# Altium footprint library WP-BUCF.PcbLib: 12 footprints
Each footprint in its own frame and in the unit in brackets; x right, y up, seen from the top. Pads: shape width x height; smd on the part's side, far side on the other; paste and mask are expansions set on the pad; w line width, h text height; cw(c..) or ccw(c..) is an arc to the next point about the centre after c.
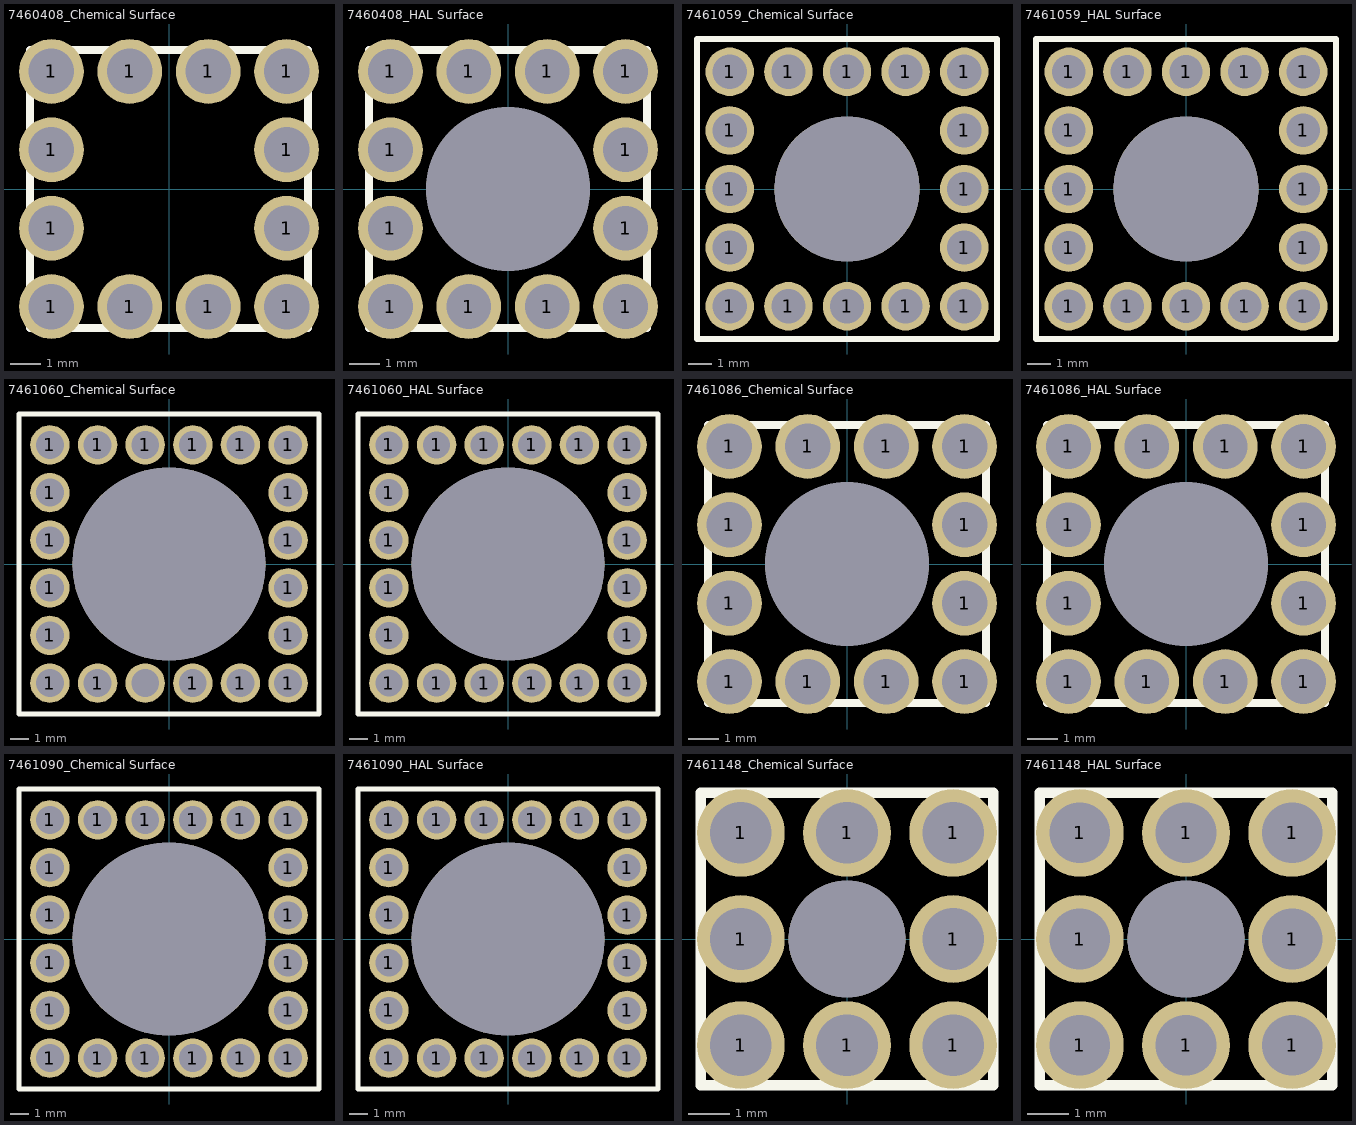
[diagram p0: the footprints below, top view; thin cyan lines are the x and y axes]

## 7460408_Chemical Surface [mm] "M5, thr 6mm"
height 9.5
pads (12):
  round 2.1 hole 1.475: 1(-3.81,-3.81) 1(-3.81,-1.27) 1(-3.81,1.27) 1(-3.81,3.81) 1(-1.27,-3.81) 1(-1.27,3.81) 1(1.27,-3.81) 1(1.27,3.81) 1(3.81,-3.81) 1(3.81,-1.27) 1(3.81,1.27) 1(3.81,3.81)
Top Overlay:
  lines w0.254: -4.5,-4.5 4.5,-4.5 4.5,4.5 -4.5,4.5 -4.5,-4.5
3D body "7460408.stp": height 6.1, standoff -3.4, extent -4.5,-4.5 4.5,4.5

## 7460408_HAL Surface [mm] "M5, thr 6mm"
height 9.5
pads (13):
  round 2.1 hole 1.45: 1(-3.81,-3.81) 1(-3.81,-1.27) 1(-3.81,1.27) 1(-3.81,3.81) 1(-1.27,-3.81) 1(-1.27,3.81) 1(1.27,-3.81) 1(1.27,3.81) 1(3.81,-3.81) 1(3.81,-1.27) 1(3.81,1.27) 1(3.81,3.81)
  round 5.3 hole 5.3 unplated: ""(0,0)
Top Overlay:
  lines w0.254: -4.5,-4.5 -4.5,4.5 4.5,4.5 4.5,-4.5 -4.5,-4.5
3D body "7460408.stp": height 6.1, standoff -3.4, extent -4.5,-4.5 4.5,4.5

## 7461059_Chemical Surface [mm] "M6, thr 13.5mm"
height 17
pads (17):
  round 2.1 hole 1.475: 1(-5.08,-5.08) 1(-5.08,-2.54) 1(-5.08,0) 1(-5.08,2.54) 1(-5.08,5.08) 1(-2.54,-5.08) 1(-2.54,5.08) 1(0,-5.08) 1(0,5.08) 1(2.54,-5.08) 1(2.54,5.08) 1(5.08,-5.08) 1(5.08,-2.54) 1(5.08,0) 1(5.08,2.54) 1(5.08,5.08)
  round 6.3 hole 6.3 unplated: ""(0,0)
Top Overlay:
  lines w0.254: -6.5,-6.5 -6.5,6.5 6.5,6.5 6.5,-6.5 -6.5,-6.5
3D body "7461059.stp": height 13.6, standoff -3.4, extent -6.5,-6.5 6.5,6.5

## 7461059_HAL Surface [mm] "M6, thr 13.5mm"
height 17
pads (17):
  round 2.1 hole 1.45: 1(-5.08,-5.08) 1(-5.08,-2.54) 1(-5.08,0) 1(-5.08,2.54) 1(-5.08,5.08) 1(-2.54,-5.08) 1(-2.54,5.08) 1(0,-5.08) 1(0,5.08) 1(2.54,-5.08) 1(2.54,5.08) 1(5.08,-5.08) 1(5.08,-2.54) 1(5.08,0) 1(5.08,2.54) 1(5.08,5.08)
  round 6.3 hole 6.3 unplated: ""(0,0)
Top Overlay:
  lines w0.254: -6.5,-6.5 6.5,-6.5 6.5,6.5 -6.5,6.5 -6.5,-6.5
3D body "7461059.stp": height 13.6, standoff -3.4, extent -6.5,-6.5 6.5,6.5

## 7461060_Chemical Surface [mm] "M10, thr 17.5mm"
height 21
pads (21):
  round 2.1 hole 1.475: 1(-6.35,-6.35) 1(-6.35,-3.81) 1(-6.35,-1.27) 1(-6.35,1.27) 1(-6.35,3.81) 1(-6.35,6.35) 1(-3.81,-6.35) 1(-3.81,6.35) 1(-1.27,6.35) 1(1.27,-6.35) 1(1.27,6.35) 1(3.81,-6.35) 1(3.81,6.35) 1(6.35,-6.35) 1(6.35,-3.81) 1(6.35,-1.27) 1(6.35,1.27) 1(6.35,3.81) 1(6.35,6.35) ""(-1.27,-6.35)
  round 10.3 hole 10.3 unplated: ""(0,0)
Top Overlay:
  lines w0.254: -8,-8 8,-8 8,8 -8,8 -8,-8
3D body "7461060.stp": height 17.6, standoff -3.4, extent -8,-8 8,8

## 7461060_HAL Surface [mm] "M10, thr 17.5mm"
height 21
pads (21):
  round 2.1 hole 1.45: 1(-6.35,-6.35) 1(-6.35,-3.81) 1(-6.35,-1.27) 1(-6.35,1.27) 1(-6.35,3.81) 1(-6.35,6.35) 1(-3.81,-6.35) 1(-3.81,6.35) 1(-1.27,-6.35) 1(-1.27,6.35) 1(1.27,-6.35) 1(1.27,6.35) 1(3.81,-6.35) 1(3.81,6.35) 1(6.35,-6.35) 1(6.35,-3.81) 1(6.35,-1.27) 1(6.35,1.27) 1(6.35,3.81) 1(6.35,6.35)
  round 10.3 hole 10.3 unplated: ""(0,0)
Top Overlay:
  lines w0.254: -8,-8 -8,8 8,8 8,-8 -8,-8
3D body "7461060.stp": height 17.6, standoff -3.4, extent -8,-8 8,8

## 7461086_Chemical Surface [mm] "M4, thr 6mm"
height 9.5
pads (13):
  round 2.1 hole 1.475: 1(-3.81,-3.81) 1(-3.81,-1.27) 1(-3.81,1.27) 1(-3.81,3.81) 1(-1.27,-3.81) 1(-1.27,3.81) 1(1.27,-3.81) 1(1.27,3.81) 1(3.81,-3.81) 1(3.81,-1.27) 1(3.81,1.27) 1(3.81,3.81)
  round 5.3 hole 5.3 unplated: ""(0,0)
Top Overlay:
  lines w0.254: -4.5,-4.5 4.5,-4.5 4.5,4.5 -4.5,4.5 -4.5,-4.5
3D body "7461086.stp": height 6.1, standoff -3.4, extent -4.5,-4.5 4.5,4.5

## 7461086_HAL Surface [mm] "M4, thr 6mm"
height 9.5
pads (13):
  round 2.1 hole 1.45: 1(-3.81,-3.81) 1(-3.81,-1.27) 1(-3.81,1.27) 1(-3.81,3.81) 1(-1.27,-3.81) 1(-1.27,3.81) 1(1.27,-3.81) 1(1.27,3.81) 1(3.81,-3.81) 1(3.81,-1.27) 1(3.81,1.27) 1(3.81,3.81)
  round 5.3 hole 5.3 unplated: ""(0,0)
Top Overlay:
  lines w0.254: -4.5,-4.5 -4.5,4.5 4.5,4.5 4.5,-4.5 -4.5,-4.5
3D body "7461086.stp": height 6.1, standoff -3.4, extent -4.5,-4.5 4.5,4.5

## 7461090_Chemical Surface [mm] "M8, thr 13.5mm"
height 17
pads (21):
  round 2.1 hole 1.475: 1(-6.35,-6.35) 1(-6.35,-3.81) 1(-6.35,-1.27) 1(-6.35,1.27) 1(-6.35,3.81) 1(-6.35,6.35) 1(-3.81,-6.35) 1(-3.81,6.35) 1(-1.27,-6.35) 1(-1.27,6.35) 1(1.27,-6.35) 1(1.27,6.35) 1(3.81,-6.35) 1(3.81,6.35) 1(6.35,-6.35) 1(6.35,-3.81) 1(6.35,-1.27) 1(6.35,1.27) 1(6.35,3.81) 1(6.35,6.35)
  round 10.3 hole 10.3 unplated: ""(0,0)
Top Overlay:
  lines w0.254: -8,-8 8,-8 8,8 -8,8 -8,-8
3D body "7461090.stp": height 13.6, standoff -3.4, extent -8,-8 8,8

## 7461090_HAL Surface [mm] "M8, thr 13.5mm"
height 17
pads (21):
  round 2.1 hole 1.45: 1(-6.35,-6.35) 1(-6.35,-3.81) 1(-6.35,-1.27) 1(-6.35,1.27) 1(-6.35,3.81) 1(-6.35,6.35) 1(-3.81,-6.35) 1(-3.81,6.35) 1(-1.27,-6.35) 1(-1.27,6.35) 1(1.27,-6.35) 1(1.27,6.35) 1(3.81,-6.35) 1(3.81,6.35) 1(6.35,-6.35) 1(6.35,-3.81) 1(6.35,-1.27) 1(6.35,1.27) 1(6.35,3.81) 1(6.35,6.35)
  round 10.3 hole 10.3 unplated: ""(0,0)
Top Overlay:
  lines w0.254: -8,-8 8,-8 8,8 -8,8 -8,-8
3D body "7461090.stp": height 13.6, standoff -3.4, extent -8,-8 8,8

## 7461148_Chemical Surface [mm] "M2.5, thr 6mm"
height 9.5
pads (9):
  round 2.1 hole 1.475: 1(-2.54,-2.54) 1(-2.54,0) 1(-2.54,2.54) 1(0,-2.54) 1(0,2.54) 1(2.54,-2.54) 1(2.54,0) 1(2.54,2.54)
  round 2.8 hole 2.8 unplated: ""(0,0)
Top Overlay:
  lines w0.254: -3.5,-3.5 3.5,-3.5 3.5,3.5 -3.5,3.5 -3.5,-3.5
3D body "7461148.stp": height 6.1, standoff -3.4, extent -3.5,-3.5 3.5,3.5

## 7461148_HAL Surface [mm] "M2.5, thr 6mm"
height 9.5
pads (9):
  round 2.1 hole 1.45: 1(-2.54,-2.54) 1(-2.54,0) 1(-2.54,2.54) 1(0,-2.54) 1(0,2.54) 1(2.54,-2.54) 1(2.54,0) 1(2.54,2.54)
  round 2.8 hole 2.8 unplated: ""(0,0)
Top Overlay:
  lines w0.254: -3.5,-3.5 3.5,-3.5 3.5,3.5 -3.5,3.5 -3.5,-3.5
3D body "7461148.stp": height 6.1, standoff -3.4, extent -3.5,-3.5 3.5,3.5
